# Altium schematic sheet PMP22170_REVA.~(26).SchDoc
size 431 x 279 mm; Date: Not shown in title block; ApprovedBy: Not shown in title block; CheckedBy: Not shown in title block; Author: Not shown in title block; CompanyName: Not shown in title block; Engineer: Not shown in title block; Organization: Not shown in title block; Address1: Not shown in title block; Address2: Not shown in title block; Address3: Not shown in title block; Address4: Not shown in title block; DocumentNumber: 1; Revision: Use project parameter SCH_Rev; SheetNumber: 1; SheetTotal: 1; PageSetup: Record=PageOptions¦CenterHorizontal=True¦CenterVertical=True¦PrintScale=1.00¦XCorrection=1.00¦YCorrection=1.00¦PrintKind=0¦BorderSize=5000000¦LeftOffset=0¦BottomOffset=0¦Orientation=2¦PaperLength=1000¦PaperWidth=1000¦Scale=100¦PaperSource=15¦PrintQuality=600¦MediaType=1¦DitherType=10¦PaperKind=Letter¦PrintScaleMode=1
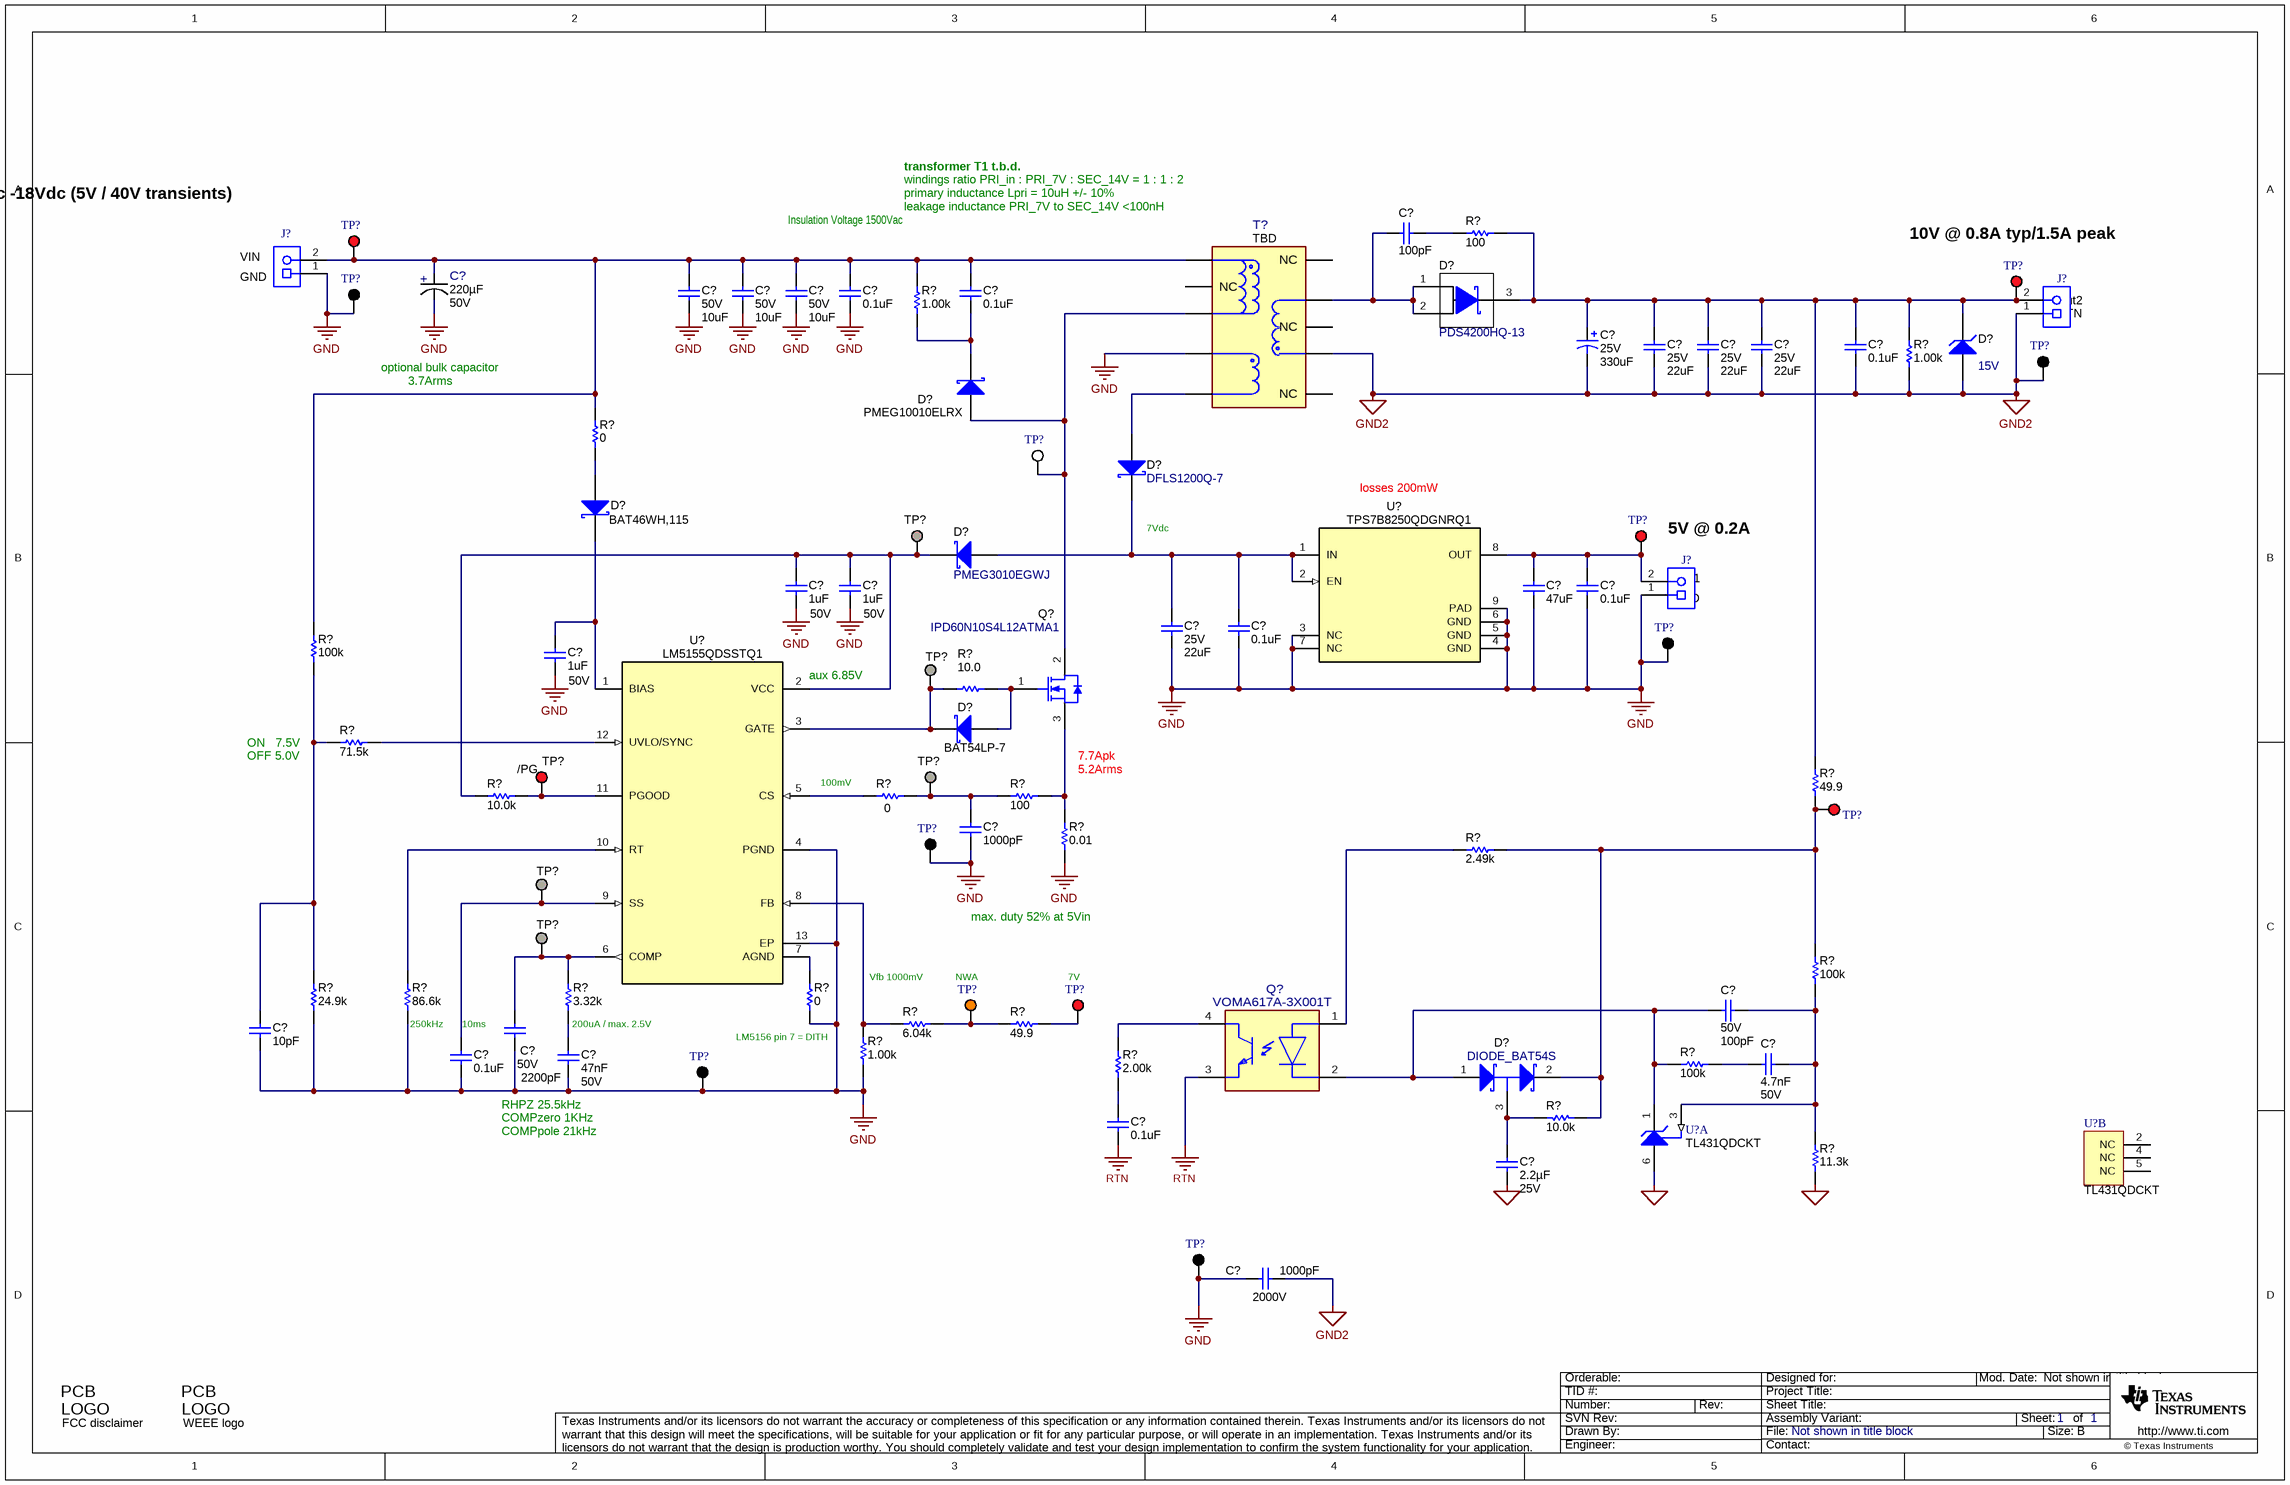
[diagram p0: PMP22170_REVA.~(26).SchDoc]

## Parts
(Parts that share a designator on the sheet are numbered #1, #2 ... from top to bottom, then left to right.)
C?#1  ValueDisplayed: 100pF  [0805_HV]  (hidden comment: Capacitor)
C?#2  Cap_F: 220µF  VDC_V: 50V  [FP-EEHZS1H221P_RADIAL_SMD-MFG]  (hidden comment: EEH-ZS1H221V)
C?#3  VDC_V: 50V  ValueDisplayed: 10uF  [1210_280]  (hidden comment: UMK325AB7106KMHT)
C?#4  VDC_V: 50V  ValueDisplayed: 10uF  [1210_280]  (hidden comment: UMK325AB7106KMHT)
C?#5  VDC_V: 50V  ValueDisplayed: 10uF  [1210_280]  (hidden comment: UMK325AB7106KMHT)
C?#6  ValueDisplayed: 0.1uF  [0603]  (hidden comment: Capacitor)
C?#7  ValueDisplayed: 0.1uF  [0603]  (hidden comment: Capacitor)
C?#8  VDC_V: 25V  ValueDisplayed: 330uF  [SM_RADIAL_10BMM]  (hidden comment: EEHZC1E331P)
C?#9  VDC_V: 25V  ValueDisplayed: 22uF  [1210_270]  (hidden comment: TMK325B7226KMHT)
C?#10  VDC_V: 25V  ValueDisplayed: 22uF  [1210_270]  (hidden comment: TMK325B7226KMHT)
C?#11  VDC_V: 25V  ValueDisplayed: 22uF  [1210_270]  (hidden comment: TMK325B7226KMHT)
C?#12  ValueDisplayed: 0.1uF  [0603]  (hidden comment: Capacitor)
C?#13  ValueDisplayed: 1uF  Value2: 50V  [0805_HV1]  (hidden comment: Capacitor)
C?#14  ValueDisplayed: 1uF  Value2: 50V  [0805_HV1]  (hidden comment: Capacitor)
C?#15  ValueDisplayed: 47uF  [1210_270]  (hidden comment: Capacitor)
C?#16  ValueDisplayed: 0.1uF  [0603]  (hidden comment: Capacitor)
C?#17  VDC_V: 25V  ValueDisplayed: 22uF  [1210_270]  (hidden comment: TMK325B7226KMHT)
C?#18  ValueDisplayed: 0.1uF  [0603]  (hidden comment: Capacitor)
C?#19  ValueDisplayed: 1uF  Value2: 50V  [0805_HV1]  (hidden comment: Capacitor)
C?#20  ValueDisplayed: 1000pF  [0603]  (hidden comment: Capacitor)
C?#21  VDC_V: 50V  ValueDisplayed: 100pF  [0603]  (hidden comment: GCM1885C1H101JA16J)
C?#22  ValueDisplayed: 10pF  [0603]  (hidden comment: Capacitor)
C?#23  VDC_V: 50V  ValueDisplayed: 2200pF  [0603]  (hidden comment: GRM188R61H222KA01D)
C?#24  ValueDisplayed: 0.1uF  [0603]  (hidden comment: Capacitor)
C?#25  Cap_F: 47nF  VDC_V: 50V  [0603]  (hidden comment: CGA3E2X7R1H473K080AA)
C?#26  Cap_F: 4.7nF  VDC_V: 50V  [0603]  (hidden comment: GCM188R71H472KA37D)
C?#27  ValueDisplayed: 0.1uF  [0603]  (hidden comment: Capacitor)
C?#28  Cap_F: 2.2µF  VDC_V: 25V  [0805_HV]  (hidden comment: CGA4J3X7R1E225K125AB)
C?#29  ValueDisplayed: 1000pF  Value2: 2000V  [1808]  (hidden comment: Capacitor)
D?#1  PDS4200HQ-13  [POWERDI5]
D?#2  value 15V  [SOD-123]  (hidden comment: MMSZ5245B-7-F)
D?#3  PartNumber: PMEG10010ELRX  [SOD-123W]  (hidden comment: DIODE_SCHOTTKY)
D?#4  DFLS1200Q-7  [PowerDI123]
D?#5  PartNumber: BAT46WH,115  [SOD-123F]  (hidden comment: DIODE_SCHOTTKY)
D?#6  PMEG3010EGWJ  [SOD-123]
D?#7  PartNumber: BAT54LP-7  [X1-DFN1006-2]  (hidden comment: DIODE_SCHOTTKY)
D?#8  DIODE_BAT54S  [SOT-523]
J?#1  Receptacle_2x1  [TERM_BLK_ED555-2DS]  (value not drawn)
J?#2  Receptacle_2x1  [TERM_BLK_ED555-2DS]  (value not drawn)
J?#3  Receptacle_2x1  [TERM_BLK_ED555-2DS]  (value not drawn)
Logo?#1  FCC disclaimer  [FCC_disclaimer]  (no BOM)
Logo?#2  WEEE logo  [WEEE_Minimum]  (no BOM)
Q?#1  IPD60N10S4L12ATMA1  [DPAK]
Q?#2  VOMA617A-3X001T  [FP-VOMA617A-3X001T_SOP4-MFG]
R?#1  ValueDisplayed: 100  [1206]  (hidden comment: CRCW1206100RFKEAHP)
R?#2  ValueDisplayed: 1.00k  [1210]  (hidden comment: ERJ14NF1001U)
R?#3  ValueDisplayed: 1.00k  [1206]  (hidden comment: CRCW12061K00FKEA)
R?#4  ValueDisplayed: 0  [0603]  (hidden comment: Resistor)
R?#5  ValueDisplayed: 100k  [0603]  (hidden comment: CRCW0603100KFKEA)
R?#6  ValueDisplayed: 10.0  [0603]  (hidden comment: Resistor)
R?#7  ValueDisplayed: 71.5k  [0603]  (hidden comment: CRCW060371K5FKEA)
R?#8  value 49.9  [0603]  (hidden comment: Resistor)
R?#9  ValueDisplayed: 10.0k  [0603]  (hidden comment: CRCW060310K0FKEA)
R?#10  ValueDisplayed: 0  [0603]  (hidden comment: Resistor)
R?#11  ValueDisplayed: 100  [0603]  (hidden comment: Resistor)
R?#12  ValueDisplayed: 0.01  [0612]  (hidden comment: ERJ-B2CFR01V)
R?#13  value 2.49k  [0603]  (hidden comment: Resistor)
R?#14  value 100k  [0603]  (hidden comment: Resistor)
R?#15  ValueDisplayed: 24.9k  [0603]  (hidden comment: CRCW060324K9FKEA)
R?#16  ValueDisplayed: 86.6k  [0603]  (hidden comment: Resistor)
R?#17  ValueDisplayed: 3.32k  [0603]  (hidden comment: CRCW06033K32FKEA)
R?#18  ValueDisplayed: 0  [0603]  (hidden comment: Resistor)
R?#19  ValueDisplayed: 6.04k  [0603]  (hidden comment: Resistor)
R?#20  ValueDisplayed: 49.9  [0603]  (hidden comment: Resistor)
R?#21  ValueDisplayed: 1.00k  [0603]  (hidden comment: Resistor)
R?#22  value 2.00k  [0603]  (hidden comment: Resistor)
R?#23  value 100k  [0603]  (hidden comment: Resistor)
R?#24  value 10.0k  [0603]  (hidden comment: Resistor)
R?#25  value 11.3k  [0603]  (hidden comment: Resistor)
T?  PartNumber: TBD  [FP-DR12-C249_SMT_12MM0_14MM5-MFG]
TP?#1  5000  [Keystone5000]  (value not drawn)
TP?#2  5000  [Keystone5000]  (value not drawn)
TP?#3  5001  [Keystone5001]  (value not drawn)
TP?#4  5001  [Keystone5001]  (value not drawn)
TP?#5  5002  [Keystone5002]  (value not drawn)
TP?#6  TP_SM_1MM  [TP_SM_1MM]  (value not drawn)  (no BOM)
TP?#7  5000  [Keystone5000]  (value not drawn)
TP?#8  5001  [Keystone5001]  (value not drawn)
TP?#9  TP_SM_1MM  [TP_SM_1MM]  (value not drawn)  (no BOM)
TP?#10  5000  [Keystone5000]  (value not drawn)
TP?#11  TP_SM_1MM  [TP_SM_1MM]  (value not drawn)  (no BOM)
TP?#12  5000  [Keystone5000]  (value not drawn)
TP?#13  5001  [Keystone5001]  (value not drawn)
TP?#14  TP_SM_1MM  [TP_SM_1MM]  (value not drawn)  (no BOM)
TP?#15  TP_SM_1MM  [TP_SM_1MM]  (value not drawn)  (no BOM)
TP?#16  5003  [Keystone5003]  (value not drawn)
TP?#17  5000  [Keystone5000]  (value not drawn)
TP?#18  5001  [Keystone5001]  (value not drawn)
TP?#19  5001  [Keystone5001]  (value not drawn)
U?#1  TPS7B8250QDGNRQ1  [DGN0008D_N]
U?#2  LM5155QDSSTQ1  [DSS0012C]
U?#3  TL431QDCKT  [DCK0006A_N]  (part B of 2)
U?#4  TL431QDCKT  [DCK0006A_N]  (part A of 2)

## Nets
GND: C?#2.1(CATHODE) C?#3.2 C?#4.2 C?#5.2 C?#6.2 C?#13.2 C?#14.2 C?#15.2 C?#16.2 C?#17.2 C?#18.2 C?#19.2 C?#20.2 C?#22.2 C?#23.2 C?#24.2 C?#25.2 C?#29.2 J?#1.1 J?#3.1 R?#12.1 R?#15.1 R?#16.1 R?#18.1 R?#21.2 T?.2(S3) TP?#3.1 TP?#8.1 TP?#13.1 TP?#18.1 TP?#19.1 U?#1.3(NC) U?#1.4(GND) U?#1.5(GND) U?#1.6(GND) U?#1.7(NC) U?#1.9(PAD) U?#2.4(PGND) U?#2.13(EP)
GND2: C?#8.2(-) C?#9.2 C?#10.2 C?#11.2 C?#12.2 C?#28.2 C?#29.1 D?#2.2(A) J?#2.1 R?#3.1 R?#25.1 T?.9(S4) TP?#4.1 U?#4.6(ANODE)
RTN: C?#27.2 Q?#2.3(EMITTER)
PG: R?#9.2 TP?#10.1 U?#2.11(PGOOD)
NetC?#1_1: C?#1.1 R?#1.1
NetC?#1_2: C?#1.2 D?#1.1(A) D?#1.2(A) T?.7
NetC?#2_2: C?#2.2(ANODE) C?#3.1 C?#4.1 C?#5.1 C?#6.1 C?#7.1 J?#1.2 R?#2.2 R?#4.2 R?#5.2 T?.5(S1,S2) TP?#1.1
NetC?#7_2: C?#7.2 D?#3.1(K) R?#2.1
NetC?#8_1: C?#8.1(+) C?#9.1 C?#10.1 C?#11.1 C?#12.1 D?#1.3(K) D?#2.1(K) J?#2.2 R?#1.2 R?#3.2 R?#8.1 TP?#2.1
NetC?#13_1: C?#13.1 C?#14.1 D?#6.1(K) R?#9.1 TP?#6.1 U?#2.2(VCC)
NetC?#15_1: C?#15.1 C?#16.1 J?#3.2 TP?#7.1 U?#1.8(OUT)
NetC?#17_1: C?#17.1 C?#18.1 D?#4.1(K) D?#6.2(A) U?#1.1(IN) U?#1.2(EN)
NetC?#19_1: C?#19.1 D?#5.1(K) U?#2.1(BIAS)
NetC?#20_1: C?#20.1 R?#10.2 R?#11.1 TP?#11.1
NetC?#21_1: C?#21.1 C?#26.1 R?#14.1 R?#25.2 U?#4.3(REF)
NetC?#21_2: C?#21.2 D?#8.1(A) Q?#2.2(CATHODE) R?#23.2 U?#4.1(CATHODE)
NetC?#22_1: C?#22.1 R?#5.1 R?#7.1 R?#15.2
NetC?#23_1: C?#23.1 R?#17.2 TP?#15.1 U?#2.6(COMP)
NetC?#24_1: C?#24.1 TP?#14.1 U?#2.9(SS)
NetC?#25_1: C?#25.1 R?#17.1
NetC?#26_2: C?#26.2 R?#23.1
NetC?#27_1: C?#27.1 R?#22.1
NetC?#28_1: C?#28.1 D?#8.3(C) R?#24.1
NetD?#3_2: D?#3.2(A) Q?#1.2(D) T?.3 TP?#5.1
NetD?#4_2: D?#4.2(A) T?.1
NetD?#5_2: D?#5.2(A) R?#4.1
NetD?#7_1: D?#7.1(K) R?#6.2 TP?#9.1 U?#2.3(GATE)
NetD?#7_2: D?#7.2(A) Q?#1.1(G) R?#6.1
NetD?#8_2: D?#8.2(K) R?#8.2 R?#13.1 R?#14.2 R?#24.2 TP?#12.1
NetQ?#1_3: Q?#1.3(S) R?#11.2 R?#12.2
NetQ?#2_1: Q?#2.1(ANODE) R?#13.2
NetQ?#2_4: Q?#2.4(COLLECTOR) R?#22.2
NetR?#7_2: R?#7.2 U?#2.12(UVLO/SYNC)
NetR?#10_1: R?#10.1 U?#2.5(CS)
NetR?#16_2: R?#16.2 U?#2.10(RT)
NetR?#18_2: R?#18.2 U?#2.7(AGND)
NetR?#19_1: R?#19.1 R?#20.1 TP?#16.1
NetR?#19_2: R?#19.2 R?#21.1 U?#2.8(FB)
NetR?#20_2: R?#20.2 TP?#17.1

Not connected (* = marked no-connect by the designer): T? 4(NC) 6(NC) 8(NC) 10(NC); U?#3 2(NC) 4(NC) 5(NC)

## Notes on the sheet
- transformer T1 t.b.d.
- Input 6Vdc -18Vdc (5V / 40V transients)
- Insulation Voltage 1500Vac
- windings ratio PRI_in : PRI_7V : SEC_14V = 1 : 1 : 2
- primary inductance Lpri = 10uH +/- 10%
- leakage inductance PRI_7V to SEC_14V <100nH
- 10V @ 0.8A typ/1.5A peak
- (near J?#1) VIN
- (near J?#1) GND
- (near J?#2) Vout2
- optional bulk capacitor
- RTN
- 3.7Arms
- losses 200mW
- (near D?#4) 7Vdc
- 5V @ 0.2A
- (near J?#3) Vout1
- (near J?#3) GND
- (near U?#2) aux 6.85V
- (near R?#7) ON   7.5V
- (near R?#7) OFF 5.0V
- (near TP?#10) /PG
- 7.7Apk
- (near R?#11) 5.2Arms
- 100mV
- (near R?#19) Vfb 1000mV
- (near TP?#16) NWA
- max. duty 52% at 5Vin
- (near TP?#17) 7V
- (near R?#16) 250kHz
- (near C?#24) 10ms
- (near R?#17) 200uA / max. 2.5V
- (near R?#18) LM5156 pin 7 = DITH
- (near C?#25) RHPZ 25.5kHz
- (near C?#25) COMPzero 1KHz
- COMPpole 21kHz

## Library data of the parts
C?#1 = CMP-0008236-2: CAP, CERM, 100 pF, 250 V, +/- 5%, C0G/NP0, 0805; PartNumber: GRM21A5C2E101JW01D; Manufacturer: MuRata; Polarized: N; Value: 100pF; U/M: EA; Value1: Unknown; VDC_V: 250V; TaMin_C: -55°C; TaMax_C: 125°C; Cap_Case: 0805; SizeArea_mm2: 2.5; SizeAreaWB_mm2: 6.75; SizeX_mm: 2; SizeY_mm: 1.25; SizeZ_mm: 1.45; AEC Category: Q200
C?#2 = CMP-0087071-1: 220µF 50V Aluminum Polymer Capacitor Radial, Can - SMD 13 mOhm 4000 Hrs @ 125°C; Manufacturer: Panasonic; SizeZ_mm: 16.8mm; AEC Grade: Grade 1; Symbol Name: SYM-EEHZS1H221P; IRMS_A: 3.7A; Tolerance_%: 20%; AEC Qualified: Yes
C?#3-C?#5 = CMP-0009258-2: CAP, CERM, 10 uF, 50 V, +/- 10%, X7R, AEC-Q200 Grade 1, 1210; Manufacturer: Taiyo Yuden; TaMin_C: -55°C; Polarized: N; SizeAreaWB_mm2: 14.7; Value1: Unknown; U/M: EA; Value: 10uF; TaMax_C: 125°C; SizeZ_mm: 2.8; SizeX_mm: 3.2; SizeY_mm: 2.5; Cap_Case: 1210; SizeArea_mm2: 8; AEC Qualified: Y; Cap_F: 10µF; AEC Grade: 1; AEC Category: Q200
C?#6 C?#7 C?#12 = CMP-0007144-4: CAP, CERM, 0.1 uF, 50 V, +/- 10%, X7R, 0603; PartNumber: GCM188R71H104KA57D; Manufacturer: MuRata; Polarized: N; Value: 0.1uF; U/M: EA; Cap_F: 100nF; ESR_ohm: 0.02; Value1: 0.02 ohm; VDC_V: 50V; IRMS_A: 1.84A; TaMin_C: -55°C; TaMax_C: 125°C; AEC Category: Q200; SizeArea_mm2: 1.28; SizeAreaWB_mm2: 4.68; SizeX_mm: 1.6; SizeY_mm: 0.8; SizeZ_mm: 1
C?#8 = CMP-0012593-3: CAP, Polymer Hybrid, 330 uF, 25 V, +/- 20%, 20 ohm, 10x10 SMD; Manufacturer: Panasonic; TaMin_C: -55°C; ESR_ohm: 20; Polarized: Y; SizeAreaWB_mm2: 159.9; Value1: 20 ohm; Value: 330uF; TaMax_C: 125°C; SizeZ_mm: 10.2; SizeX_mm: 11; SizeY_mm: 10.3; SizeArea_mm2: 113.3; CompType: Capacitor; Cap_F: 330µF; IRMS_A: 2A; AEC Category: Q200
C?#9-C?#11 C?#17 = CMP-0009255-2: CAP, CERM, 22 uF, 25 V, +/- 10%, X7R, AEC-Q200 Grade 1, 1210; Manufacturer: Taiyo Yuden; TaMin_C: -55°C; Polarized: N; SizeAreaWB_mm2: 14.7; Value1: Unknown; U/M: EA; Value: 22uF; TaMax_C: 125°C; SizeZ_mm: 2.7; SizeX_mm: 3.2; SizeY_mm: 2.5; Cap_Case: 1210; SizeArea_mm2: 8; AEC Qualified: Y; Cap_F: 22µF; AEC Grade: 1; AEC Category: Q200
C?#13 C?#14 C?#19 = CMP-0008350-2: CAP, CERM, 1 uF, 50 V, +/- 10%, X7R, 0805; PartNumber: GRM21BR71H105KA12L; Manufacturer: MuRata; Polarized: N; Value: 1uF; U/M: EA; Cap_F: 1µF; Value1: Unknown; TaMin_C: -55°C; TaMax_C: 125°C; Cap_Case: 0805; SizeArea_mm2: 2.5; SizeAreaWB_mm2: 6.75; SizeX_mm: 2; SizeY_mm: 1.25; SizeZ_mm: 1.45; AEC Category: Q200
C?#15 = CMP-0009220-2: CAP, CERM, 47 uF, 10 V, +/- 10%, X7R, 1210; PartNumber: GRM32ER71A476KE15L; Manufacturer: MuRata; Polarized: N; Value: 47uF; U/M: EA; Cap_F: 47µF; Value1: Unknown; VDC_V: 10V; TaMin_C: -55°C; TaMax_C: 125°C; Cap_Case: 1210; SizeArea_mm2: 8; SizeAreaWB_mm2: 14.7; SizeX_mm: 3.2; SizeY_mm: 2.5; SizeZ_mm: 2.7; AEC Category: Q200
C?#16 C?#18 C?#24 = CMP-0007378-5: CAP, CERM, 0.1 uF, 16 V, +/- 10%, X7R, 0603; PartNumber: GRM188R71C104KA01D; Manufacturer: MuRata; Polarized: N; Value: 0.1uF; U/M: EA; Cap_F: 100nF; Value1: Unknown; VDC_V: 16V; TaMin_C: -55°C; TaMax_C: 125°C; SizeArea_mm2: 1.28; SizeAreaWB_mm2: 4.68; SizeX_mm: 1.6; SizeY_mm: 0.8; SizeZ_mm: 1; AEC Category: Q200
C?#20 = CMP-0007402-4: CAP, CERM, 1000 pF, 25 V, +/- 10%, X7R, 0603; PartNumber: GRM188R71E102KA01D; Manufacturer: MuRata; Polarized: N; Value: 1000pF; U/M: EA; Cap_F: 1nF; Value1: Unknown; VDC_V: 25V; TaMin_C: -55°C; TaMax_C: 125°C; SizeArea_mm2: 1.28; SizeAreaWB_mm2: 4.68; SizeX_mm: 1.6; SizeY_mm: 0.8; SizeZ_mm: 1; AEC Category: Q200
C?#21 = CMP-0750041-1: CAP, CERM, 100 pF, 50 V,+/- 5%, C0G/NP0, AEC-Q200 Grade 1, 0603; Manufacturer: MuRata; AEC Grade: 1; SizeArea_mm2: 1.28; SizeX_mm: 1.6; Polarized: N; TaMax_C: 125°C; Value: 100pF; U/M: EA; AEC Qualified: Y; SizeAreaWB_mm2: 4.68; TaMin_C: -55°C; SizeY_mm: 0.8; AEC Category: Q200
C?#22 = CMP-0007170-4: CAP, CERM, 10 pF, 50 V, +/- 5%, C0G/NP0, 0603; PartNumber: GRM1885C1H100JA01D; Manufacturer: MuRata; Polarized: N; Value: 10pF; U/M: EA; Value1: Unknown; VDC_V: 50V; TaMin_C: -55°C; TaMax_C: 125°C; SizeArea_mm2: 1.28; SizeAreaWB_mm2: 4.68; SizeX_mm: 1.6; SizeY_mm: 0.8; SizeZ_mm: 1; AEC Category: Q200
C?#23 = CMP-0007351-3: CAP, CERM, 2200 pF, 50 V, +/- 10%, X5R, 0603; Manufacturer: MuRata; TaMin_C: -55°C; Polarized: N; SizeAreaWB_mm2: 4.68; Value1: Unknown; U/M: EA; Value: 2200pF; TaMax_C: 85°C; SizeZ_mm: 1; SizeX_mm: 1.6; SizeY_mm: 0.8; SizeArea_mm2: 1.28; Cap_F: 2.2nF; AEC Category: Q200
C?#25 = CMP-0007079-4: CAP, CERM, 0.047 uF, 50 V, +/- 10%, X7R, AEC-Q200 Grade 1, 0603; Manufacturer: TDK; TaMin_C: -55°C; ESR_ohm: 0.049007; Polarized: N; SizeAreaWB_mm2: 4.68; Value1: 0.049007 ohm; U/M: EA; TaMax_C: 125°C; SizeZ_mm: 1; SizeX_mm: 1.6; SizeY_mm: 0.8; SizeArea_mm2: 1.28; AEC Qualified: Y; IRMS_A: 767.528mA; AEC Category: Q200
C?#26 = CMP-0007146-4: CAP, CERM, 4700 pF, 50 V, +/- 10%, X7R, AEC-Q200 Grade 1, 0603; Manufacturer: MuRata; TaMin_C: -55°C; Polarized: N; SizeAreaWB_mm2: 4.68; Value1: Unknown; U/M: EA; Value: 4700pF; TaMax_C: 125°C; SizeZ_mm: 1; SizeX_mm: 1.6; SizeY_mm: 0.8; SizeArea_mm2: 1.28; AEC Qualified: Y; AEC Category: Q200
C?#27 = CMP-0007469-4: CAP, CERM, 0.1 uF, 100 V, +/- 10%, X7R, 0603; PartNumber: GRM188R72A104KA35D; Manufacturer: MuRata; Polarized: N; Value: 0.1uF; U/M: EA; Cap_F: 100nF; Value1: Unknown; VDC_V: 100V; TaMin_C: -55°C; TaMax_C: 125°C; AEC Category: Q200; SizeArea_mm2: 1.28; SizeAreaWB_mm2: 4.68; SizeX_mm: 1.6; SizeY_mm: 0.8; SizeZ_mm: 1
C?#28 = CMP-0007975-2: CAP, CERM, 2.2 uF, 25 V, +/- 10%, X7R, AEC-Q200 Grade 1, 0805; Manufacturer: TDK; TaMin_C: -55°C; Polarized: N; SizeAreaWB_mm2: 6.75; Value1: Unknown; U/M: EA; Value: 2.2uF; TaMax_C: 125°C; SizeZ_mm: 1.45; SizeX_mm: 2; SizeY_mm: 1.25; Cap_Case: 0805; SizeArea_mm2: 2.5; AEC Qualified: Y; AEC Grade: 1; AEC Category: Q200
C?#29 = CMP-0009436-2: CAP, CERM, 1000 pF, 2000 V, +/- 10%, X7R, 1808; PartNumber: GR442QR73D102KW01L; Manufacturer: MuRata; Polarized: N; Value: 1000pF; U/M: EA; Cap_F: 1nF; Value1: Unknown; VDC_V: 2kV; TaMin_C: -55°C; TaMax_C: 125°C; SizeArea_mm2: 9; SizeAreaWB_mm2: 16.5; SizeX_mm: 4.5; SizeY_mm: 2; SizeZ_mm: 2.03; AEC Category: Q200
D?#1 = CMP-0081019-2: Diode, Schottky, 200 V, 4 A, AEC-Q101, PowerDI5; Manufacturer: Diodes Inc.; Vf_V: 840mV; Io_A: 4A; SizeX_mm: 6.4; Vr_V: 200V; Value2: 0.84V; AEC Category: Q101; TJmax_C: 175°C; SizeAreaWB_mm2: 49.56; SizeArea_mm2: 24.96; Value: 200V; AEC Qualified: Y; SizeY_mm: 3.9; SizeZ_mm: 1.05
D?#2 = CMP-0005753-1: Diode, Zener, 15 V, 500 mW, SOD-123; Manufacturer: Diodes Inc.; Power_W: 500mW; SizeAreaWB_mm2: 13.095; Value1: 0.5W; RJA_CperW: 350; U/M: EA; SizeZ_mm: 1.35; SizeX_mm: 3.85; SizeY_mm: 1.7; SizeArea_mm2: 6.545; AEC Category: Q101
D?#3 = CMP-0028782-2: Diode, Schottky, 100 V, 1 A, AEC-Q101, SOD-123W; Manufacturer: Nexperia; Vf_V: 770mV; Value: 100V; Value1: 1A; Value2: 0.77V; TJmax_C: 175°C; SizeAreaWB_mm2: 12.15; SizeArea_mm2: 5.95; SizeX_mm: 3.5; SizeY_mm: 1.7; SizeZ_mm: 1; AEC Category: Q101; AEC Qualified: Y; Green_Lifecycle: Not Set; Green_REACh: Incomplete
D?#4 = CMP-0028517-2: Diode, Schottky, 200 V, 1 A, PowerDI123; Manufacturer: Diodes Inc.; Vr_V: 200V; SizeZ_mm: 0.98; Value: 200V; TJmax_C: 175°C; SizeY_mm: 1.78; Vf_V: 850mV; Green_REACh: Passed; Io_A: 1A; Value2: 0.85V; SizeAreaWB_mm2: 13.066; SizeArea_mm2: 6.586; Green_Lifecycle: Active; AEC Category: Q101; SizeX_mm: 3.7; RJC_CperW: 7
D?#5 = CMP-0028632-2: Diode, Schottky, 100 V, 0.25 A, SOD-123F; Manufacturer: Nexperia; Vf_V: 850mV; Value: 100V; Value1: 0.25A; Value2: 0.85V; Io_A: 250mA; TJmax_C: 150°C; SizeAreaWB_mm2: 11.7; SizeArea_mm2: 5.6; SizeX_mm: 3.5; SizeY_mm: 1.6; SizeZ_mm: 1.1; AEC Category: Q101; Green_Lifecycle: Not Set; Green_REACh: Incomplete
D?#6 = CMP-0079240-2: Diode, Schottky, 30 V, 1 A, AEC-Q101, SOD-123; Manufacturer: Nexperia; SizeZ_mm: 1.35; Value: 30V; Value1: 1A; AEC Category: Q101; Vf_V: 560mV; SizeX_mm: 3.85; SizeAreaWB_mm2: 13.095; Value2: 0.56V; SizeY_mm: 1.7; AEC Qualified: Y; TJmax_C: 150°C; SizeArea_mm2: 6.545
D?#7 = CMP-0076931-2: Diode, Schottky, 30 V, 0.2 A, 1.00x0.50x0.60mm; Manufacturer: Diodes Inc.; Vf_V: 1V; Value: 30V; Value1: 0.2A; Io_A: 200mA; SizeAreaWB_mm2: 3.2; SizeArea_mm2: 0.6; SizeX_mm: 1.0; SizeZ_mm: 0.53; AEC Category: Q101; Green_Lifecycle: Not Set; Green_REACh: Incomplete
D?#8 = CMP-0028641-2: Diode, Schottky, 30 V, 0.2 A, SOT-523; PartNumber: BAT54ST-7-F; Manufacturer: Diodes Inc.; Vf_V: 1V; Value: 30V; Value1: 0.2A; Io_A: 200mA; TJmax_C: 125°C; AEC Category: Q101; Green_Lifecycle: Not Set; Green_REACh: Incomplete; SizeArea_mm2: 2.56; SizeAreaWB_mm2: 6.76; SizeX_mm: 1.6; SizeZ_mm: 0.8
J?#1-J?#3 = CMP-0074913-1: Terminal Block, 3.5mm Pitch, 2x1, TH; PartNumber: ED555/2DS; Manufacturer: On-Shore Technology; Cert_CULUS: Y; CNHeader: False; ContactFinish: Brass; CT: True; Current_A: 6A; Gender: Female; Green_Lifecycle: Active; Green_REACh: Passed; Pitch_mm: 3.5; Row_Count: 1; Shrouded: N; Voltage_V: 150V
Logo?#1 = CMP-0074847-1: FCC_disclaimer; Library Reference: Logo
Logo?#2 = CMP-0074769-1
Q?#1 = CMP-0080670-2: MOSFET, N-CH, 100 V, 60 A, AEC-Q101, DPAK; Manufacturer: Infineon Technologies; Alternate Manufacturer: None; QgTyp_nC: 38; AEC Category: Q101; Vgs_V: 16V; Value1: 0.015 ohm; SizeAreaWB_mm2: 101.7114; IdsMax_A: 60A; SizeX_mm: 9.91; SizeArea_mm2: 64.8114; Value: 100V; Value2: 38 nC; Rdson45_ohm: 0.015; SizeY_mm: 6.54; ChType: N; AEC Qualified: Y; ChMode: Enhancement; SizeZ_mm: 2.29
Q?#2 = CMP-0087531-1: Optoisolator Transistor Output 3750Vrms 1 Channel 4-SOP; Manufacturer: Vishay; SizeZ_mm: 2.42mm; CTR (Min): 100%; CTR (Max): 200%
R?#1 = CMP-0016570-3: RES, 100, 1%, 0.5 W, AEC-Q200 Grade 0, 1206; Manufacturer: Vishay-Dale; Power_W: 500mW; TempCo: 100 ppm/C; Value_Code: 100R; Value: 100; EIA_Code: E96; SizeX_mm: 3.2; SizeY_mm: 1.6; SizeZ_mm: 1.35; Value2: 0.5W; SizeArea_mm2: 5.12; AEC Qualified: Y; AEC Grade: 0; AEC Category: Q200
R?#2 = CMP-0015030-3: RES, 1.00 k, 1%, 0.5 W, AEC-Q200 Grade 0, 1210; Manufacturer: Panasonic; Power_W: 500mW; TempCo: 100 ppm/C; SizeAreaWB_mm2: 14.7; Value_Code: 1k00; Value: 1.00k; EIA_Code: E96; Res_ohm: 1k; SizeX_mm: 3.2; SizeY_mm: 2.5; SizeZ_mm: 1.35; Value2: 0.5W; SizeArea_mm2: 8; AEC Qualified: Y; VDC_V: 22V; AEC Category: Q200; AEC Grade: 0
R?#3 = CMP-0016687-3: RES, 1.00 k, 1%, 0.25 W, AEC-Q200 Grade 0, 1206; Manufacturer: Vishay-Dale; Power_W: 250mW; TempCo: 100 ppm/C; Value_Code: 1k00; Value: 1.00k; EIA_Code: E96; Res_ohm: 1k; SizeX_mm: 3.2; SizeY_mm: 1.6; SizeZ_mm: 1.35; Value2: 0.25W; SizeArea_mm2: 5.12; AEC Qualified: Y; VDC_V: 200V; AEC Category: Q200; AEC Grade: 0
R?#4 R?#10 R?#18 = CMP-0025697-4: RES, 0, 5%, 0.1 W, AEC-Q200 Grade 0, 0603; PartNumber: CRCW06030000Z0EA; Manufacturer: Vishay-Dale; Value: 0; Value_Code: 0000; Power_W: 100mW; Value2: 0.1W; VDC_V: 75V; TempCo: 200 ppm/C; SizeArea_mm2: 1.28; SizeX_mm: 1.6; SizeY_mm: 0.8; SizeZ_mm: 1; EIA_Code: E24; AEC Category: Q200; AEC Qualified: Y
R?#5 = CMP-0021990-4: RES, 100 k, 1%, 0.1 W, AEC-Q200 Grade 0, 0603; Manufacturer: Vishay-Dale; Power_W: 100mW; TempCo: 100 ppm/C; Value: 100k; EIA_Code: E96; SizeX_mm: 1.6; SizeY_mm: 0.8; SizeZ_mm: 1; Value2: 0.1W; SizeArea_mm2: 1.28; AEC Qualified: Y; VDC_V: 75V; AEC Category: Q200; AEC Grade: 0
R?#6 = CMP-0022003-4: RES, 10.0, 1%, 0.1 W, AEC-Q200 Grade 0, 0603; PartNumber: CRCW060310R0FKEA; Manufacturer: Vishay-Dale; Value: 10.0; Res_ohm: 10; Value_Code: 10R0; Power_W: 100mW; Value2: 0.1W; VDC_V: 75V; TempCo: 100 ppm/C; SizeArea_mm2: 1.28; SizeX_mm: 1.6; SizeY_mm: 0.8; SizeZ_mm: 1; EIA_Code: E96; AEC Category: Q200; AEC Qualified: Y; AEC Grade: 0
R?#7 = CMP-0022581-4: RES, 71.5 k, 1%, 0.1 W, AEC-Q200 Grade 0, 0603; Manufacturer: Vishay-Dale; Power_W: 100mW; TempCo: 100 ppm/C; Value_Code: 71k5; Value: 71.5k; EIA_Code: E96; SizeX_mm: 1.6; SizeY_mm: 0.8; SizeZ_mm: 1; Value2: 0.1W; SizeArea_mm2: 1.28; AEC Qualified: Y; VDC_V: 75V; AEC Category: Q200; AEC Grade: 0
R?#8 = CMP-0022448-4: RES, 49.9, 1%, 0.1 W, AEC-Q200 Grade 0, 0603; PartNumber: CRCW060349R9FKEA; Manufacturer: Vishay-Dale; Value_Code: 49R9; Power_W: 100mW; Value2: 0.1W; VDC_V: 75V; TempCo: 100 ppm/C; EIA_Code: E96; AEC Category: Q200; AEC Grade: 0; AEC Qualified: Y; SizeArea_mm2: 1.28; SizeX_mm: 1.6; SizeY_mm: 0.8; SizeZ_mm: 1
R?#9 = CMP-0021998-4: RES, 10.0 k, 1%, 0.1 W, AEC-Q200 Grade 0, 0603; Manufacturer: Vishay-Dale; Power_W: 100mW; TempCo: 100 ppm/C; Value_Code: 10k0; Value: 10.0k; EIA_Code: E96; Res_ohm: 10k; SizeX_mm: 1.6; SizeY_mm: 0.8; SizeZ_mm: 1; Value2: 0.1W; SizeArea_mm2: 1.28; AEC Qualified: Y; VDC_V: 75V; AEC Category: Q200; AEC Grade: 0
R?#11 = CMP-0021991-4: RES, 100, 1%, 0.1 W, AEC-Q200 Grade 0, 0603; PartNumber: CRCW0603100RFKEA; Manufacturer: Vishay-Dale; Value: 100; Value_Code: 100R; Power_W: 100mW; Value2: 0.1W; VDC_V: 75V; TempCo: 100 ppm/C; SizeArea_mm2: 1.28; SizeX_mm: 1.6; SizeY_mm: 0.8; SizeZ_mm: 1; EIA_Code: E96; AEC Category: Q200; AEC Qualified: Y; AEC Grade: 0
R?#12 = CMP-0015054-2: RES, 0.01, 1%, 1 W, AEC-Q200 Grade 0, 0612; Manufacturer: Panasonic; Power_W: 1W; TempCo: 300 ppm/C; SizeAreaWB_mm2: 10.92; Value_Code: R010; U/M: EA; Value: 0.01; EIA_Code: E96; SizeX_mm: 1.6; SizeY_mm: 3.2; SizeZ_mm: 0.85; SizeArea_mm2: 5.12; AEC Qualified: Y; AEC Grade: 0; AEC Category: Q200
R?#13 = CMP-0022277-4: RES, 2.49 k, 1%, 0.1 W, AEC-Q200 Grade 0, 0603; PartNumber: CRCW06032K49FKEA; Manufacturer: Vishay-Dale; Value_Code: 2k49; Power_W: 100mW; Value2: 0.1W; VDC_V: 75V; TempCo: 100 ppm/C; EIA_Code: E96; AEC Category: Q200; AEC Grade: 0; AEC Qualified: Y; SizeArea_mm2: 1.28; SizeX_mm: 1.6; SizeY_mm: 0.8; SizeZ_mm: 1
R?#14 R?#23 = CMP-0021990-4: RES, 100 k, 1%, 0.1 W, AEC-Q200 Grade 0, 0603; PartNumber: CRCW0603100KFKEA; Manufacturer: Vishay-Dale; Power_W: 100mW; Value2: 0.1W; VDC_V: 75V; TempCo: 100 ppm/C; EIA_Code: E96; AEC Category: Q200; AEC Grade: 0; AEC Qualified: Y; SizeArea_mm2: 1.28; SizeX_mm: 1.6; SizeY_mm: 0.8; SizeZ_mm: 1
R?#15 = CMP-0022237-4: RES, 24.9 k, 1%, 0.1 W, AEC-Q200 Grade 0, 0603; Manufacturer: Vishay-Dale; Power_W: 100mW; TempCo: 100 ppm/C; Value_Code: 24k9; Value: 24.9k; EIA_Code: E96; SizeX_mm: 1.6; SizeY_mm: 0.8; SizeZ_mm: 1; Value2: 0.1W; SizeArea_mm2: 1.28; AEC Qualified: Y; VDC_V: 75V; AEC Category: Q200; AEC Grade: 0
R?#16 = CMP-0022628-4: RES, 86.6 k, 1%, 0.1 W, AEC-Q200 Grade 0, 0603; PartNumber: CRCW060386K6FKEA; Manufacturer: Vishay-Dale; Value: 86.6k; Value_Code: 86k6; Power_W: 100mW; Value2: 0.1W; VDC_V: 75V; TempCo: 100 ppm/C; SizeArea_mm2: 1.28; SizeX_mm: 1.6; SizeY_mm: 0.8; SizeZ_mm: 1; EIA_Code: E96; AEC Category: Q200; AEC Qualified: Y; AEC Grade: 0
R?#17 = CMP-0022375-4: RES, 3.32 k, 1%, 0.1 W, AEC-Q200 Grade 0, 0603; Manufacturer: Vishay-Dale; Power_W: 100mW; TempCo: 100 ppm/C; Value_Code: 3k32; Value: 3.32k; EIA_Code: E96; SizeX_mm: 1.6; SizeY_mm: 0.8; Value2: 0.1W; SizeArea_mm2: 1.28; AEC Qualified: Y; VDC_V: 75V; AEC Category: Q200; SizeZ_mm: 1; AEC Grade: 0
R?#19 = CMP-0022558-4: RES, 6.04 k, 1%, 0.1 W, AEC-Q200 Grade 0, 0603; PartNumber: CRCW06036K04FKEA; Manufacturer: Vishay-Dale; Value: 6.04k; Value_Code: 6k04; Power_W: 100mW; Value2: 0.1W; VDC_V: 75V; TempCo: 100 ppm/C; SizeArea_mm2: 1.28; SizeX_mm: 1.6; SizeY_mm: 0.8; SizeZ_mm: 1; EIA_Code: E96; AEC Category: Q200; AEC Qualified: Y; AEC Grade: 0
R?#20 = CMP-0022448-4: RES, 49.9, 1%, 0.1 W, AEC-Q200 Grade 0, 0603; PartNumber: CRCW060349R9FKEA; Manufacturer: Vishay-Dale; Value: 49.9; Value_Code: 49R9; Power_W: 100mW; Value2: 0.1W; VDC_V: 75V; TempCo: 100 ppm/C; SizeArea_mm2: 1.28; SizeX_mm: 1.6; SizeY_mm: 0.8; SizeZ_mm: 1; EIA_Code: E96; AEC Category: Q200; AEC Qualified: Y; AEC Grade: 0
R?#21 = CMP-0022109-5: RES, 1.00 k, 1%, 0.1 W, AEC-Q200 Grade 0, 0603; PartNumber: CRCW06031K00FKEA; Manufacturer: Vishay-Dale; Value: 1.00k; Res_ohm: 1k; Value_Code: 1k00; Power_W: 100mW; Value2: 0.1W; VDC_V: 75V; TempCo: 100 ppm/C; EIA_Code: E96; AEC Category: Q200; AEC Grade: 0; AEC Qualified: Y; SizeArea_mm2: 1.28; SizeX_mm: 1.6; SizeY_mm: 0.8; SizeZ_mm: 1
R?#22 = CMP-0022268-4: RES, 2.00 k, 1%, 0.1 W, AEC-Q200 Grade 0, 0603; PartNumber: CRCW06032K00FKEA; Manufacturer: Vishay-Dale; Res_ohm: 2k; Value_Code: 2k00; Power_W: 100mW; Value2: 0.1W; VDC_V: 75V; TempCo: 100 ppm/C; EIA_Code: E96; AEC Category: Q200; AEC Grade: 0; AEC Qualified: Y; SizeArea_mm2: 1.28; SizeX_mm: 1.6; SizeY_mm: 0.8; SizeZ_mm: 1
R?#24 = CMP-0021998-4: RES, 10.0 k, 1%, 0.1 W, AEC-Q200 Grade 0, 0603; PartNumber: CRCW060310K0FKEA; Manufacturer: Vishay-Dale; Res_ohm: 10k; Value_Code: 10k0; Power_W: 100mW; Value2: 0.1W; VDC_V: 75V; TempCo: 100 ppm/C; EIA_Code: E96; AEC Category: Q200; AEC Grade: 0; AEC Qualified: Y; SizeArea_mm2: 1.28; SizeX_mm: 1.6; SizeY_mm: 0.8; SizeZ_mm: 1
R?#25 = CMP-0022017-4: RES, 11.3 k, 1%, 0.1 W, AEC-Q200 Grade 0, 0603; PartNumber: CRCW060311K3FKEA; Manufacturer: Vishay-Dale; Value_Code: 11k3; Power_W: 100mW; Value2: 0.1W; VDC_V: 75V; TempCo: 100 ppm/C; EIA_Code: E96; AEC Category: Q200; AEC Grade: 0; AEC Qualified: Y; SizeArea_mm2: 1.28; SizeX_mm: 1.6; SizeY_mm: 0.8; SizeZ_mm: 1
T? = CMP-0087431-1: TRANSFORMER, 7uH; Ind_H: 7µH
TP?#1 TP?#2 TP?#7 TP?#10 TP?#12 TP?#17 = CMP-0055137-1: Test Point, Miniature, Red, TH; Manufacturer: Keystone; CNHeader: FALSE; ContactFinish: Silver; CT: TRUE; Green_Lifecycle: Active; Green_REACh: Passed
TP?#3 TP?#4 TP?#8 TP?#13 TP?#18 TP?#19 = CMP-0055138-1: Test Point, Miniature, Black, TH; Manufacturer: Keystone; CNHeader: FALSE; ContactFinish: Silver; CT: TRUE; Green_Lifecycle: Active; Green_REACh: Passed
TP?#5 = CMP-0055139-1: Test Point, Miniature, White, TH; Manufacturer: Keystone; ContactFinish: Silver; CNHeader: FALSE; CT: TRUE; Green_Lifecycle: Active; Green_REACh: Passed
TP?#6 TP?#9 TP?#11 TP?#14 TP?#15 = CMP-0003825-1: 1mm Test Point, SMT; Manufacturer: Any
TP?#16 = CMP-0055140-1: Test Point, Miniature, Orange, TH; Manufacturer: Keystone; ContactFinish: Silver; CNHeader: FALSE; CT: TRUE; Green_Lifecycle: Active; Green_REACh: Passed
U?#1 = CMP-0013313-4: 300mA High-Voltage Ultra-Low-Iq Low-Dropout (LDO) Regulator, DGN0008D (VSSOP-8); Manufacturer: Texas Instruments; SizeX_mm: 5.05; SizeY_mm: 3.1; CompType: IC; SizeZ_mm: 1.1; SizeArea_mm2: 15.655; SizeAreaWB_mm2: 35.955; AEC Category: Q200; AEC Qualified: Y
U?#2 = CMP-0081538-1: Automotive Grade 2.2-MHz Wide Input Non-synchronous Boost Controller, DSS0012C (WSON-12); Alternate PartNumber: LM5155QDSSRQ1; Alternate Manufacturer: Texas Instruments; SizeAreaWB_mm2: 12; SizeZ_mm: 0.8; SizeX_mm: 2; SizeY_mm: 3; SizeArea_mm2: 6; CompType: IC; AEC Qualified: Y; AEC Category: Q200
U?#3 U?#4 = CMP-0033197-3: 2% Accuracy Adjustable Precision Shunt Regulator, DCK0006A (SOT-SC70-6); Manufacturer: Texas Instruments; VO Adj(Max)(V): 36; Initial Accuracy @ 25/deg C(%): 2; Eco-Plan: Green (RoHS & no Sb/Br); Iout/Iz(Max)(mA): 100; Rating: Catalog; Temp Coeff(Max)(ppm/ degree C): 92; VO Adj(Min)(V): 2.495; Temp Coeff(Typ)(ppm/ degree C): 34; Min Iz for Regulation(uA): 600; AEC Category: Q200; AEC Qualified: N; CompType: IC; SizeAreaWB_mm2: 9.3; SizeArea_mm2: 4.2; SizeX_mm: 2.1; SizeY_mm: 2.0; SizeZ_mm: 1.1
